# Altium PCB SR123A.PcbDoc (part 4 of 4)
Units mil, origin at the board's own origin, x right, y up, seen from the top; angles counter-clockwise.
Board outline 5500 x 3200 mil, 4 copper layers (Top Layer, Signal Layer 1, Signal Layer 2, Bottom Layer), stack 64.312 mil thick; 295 components, 105 nets, 659 pads, 1365 vias.
Unrouted connection lines stored in the file: 735.
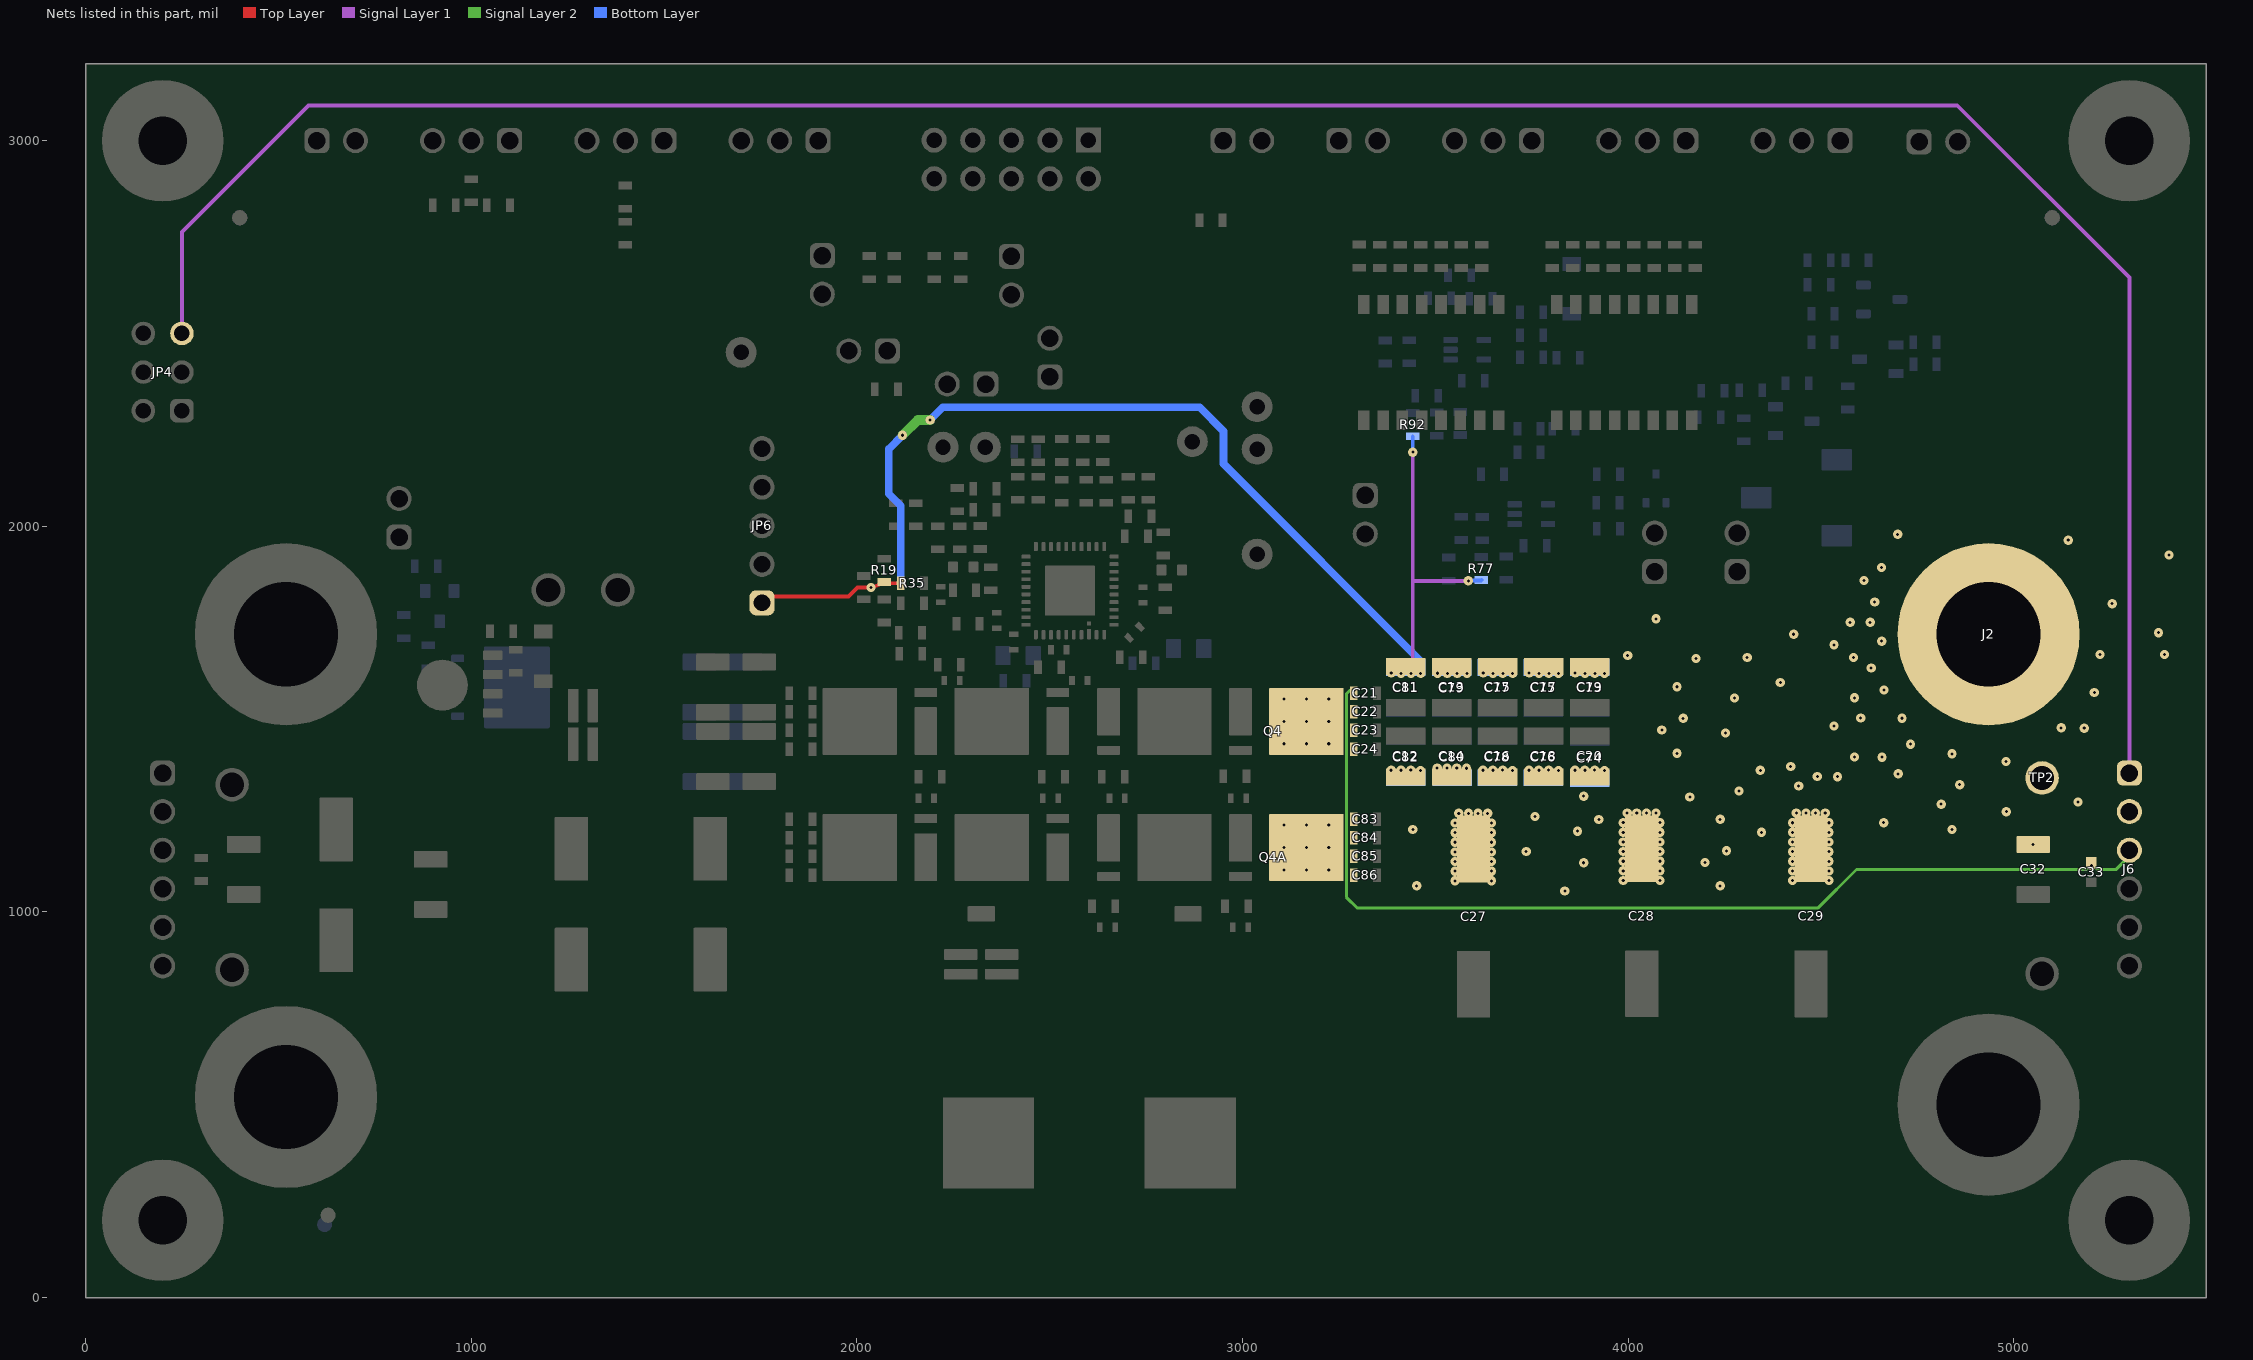
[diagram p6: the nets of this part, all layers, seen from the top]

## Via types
v1: diameter 24, hole 7.87, Top Layer to Bottom Layer, tented both sides, 520 vias
v2: diameter 16, hole 8, Top Layer to Bottom Layer, tented both sides, 418 vias
v3: diameter 24, hole 8, Top Layer to Bottom Layer, tented both sides, 412 vias
v4: diameter 19.68, hole 7.87, Top Layer to Bottom Layer, tented both sides, 12 vias
v5: diameter 16, hole 7.87, Top Layer to Bottom Layer, tented both sides, 2 vias
v6: diameter 34, hole 16, Top Layer to Bottom Layer, tented both sides, 1 vias

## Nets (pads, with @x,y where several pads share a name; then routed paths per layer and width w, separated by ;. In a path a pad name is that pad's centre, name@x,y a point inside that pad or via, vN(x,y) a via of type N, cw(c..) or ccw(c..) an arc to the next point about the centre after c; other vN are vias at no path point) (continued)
VOUT: C11.2 C12.2 C13.2 C14.2 C15.1 C16.1 C17.1 C18.1 C19.1 C20.1 C21.1 C22.1 C23.1 C24.1 C27.2 C28.2 C29.2 C32.2 C33.1 C73.2 C74.2 C75.2 C76.2 C77.1 C78.2 C79.1 C80.1 C81.2 C82.1 C83.2 C84.2 C85.2 C86.2 J2.1 J6.1 J6.2 J6.3 JP4.5 JP6.1 Q4.5-6-7-8 Q4A.5-6-7-8 R19.2 R35.2 R77.2 R92.2 TP2.1 | length 12852.1
  Top Layer w10: JP6.1@1754.31,1801.32 1770.55,1817.56 1978.28,1817.56 2001.74,1841.01 v1(2037.13,1841.01) 2057.47,1848.65 R19.2@2058.29,1848.65 ; R19.2@2081.16,1852.1 2083.29,1852.13 2109.38,1852.6 v3(2114.38,1852.68)
  Signal Layer 1 w10: JP4.5@250,2500 250,2763 578.29,3091.29 4853.71,3091.29 5300,2645 J6.1@5300,1380 ; v1(3441.84,2192.2) 3441.84,1858.5 ; v3(3462.26,1618.71) 3441.84,1618.71 3439.64,1620.91 3439.64,1629.37 3441.84,1631.57 3441.84,1858.5 ; v1(3585.87,1858.5) 3441.84,1858.5
  Signal Layer 2 w8: v2(3289.18,1576.12) 3287.64,1574.59 3279.03,1574.59 3269.67,1565.23 3269.67,1038.33 3298.4,1009.6 4491.84,1009.61 4592.25,1110.01 5189.1,1110.02 5199.4,1120.32 5206.12,1120.32 5215.99,1110.45 5266.2,1110.45 5284.42,1128.67 5284.42,1129.01 5300,1144.59 J6.3@5300,1160
  Signal Layer 2 w25: v3(2118.65,2236.09) 2158.3,2275.74 v3(2190.2,2275.74)
  Bottom Layer w10: v1(3441.84,2192.2) R92.2@3441.84,2233.59 ; v1(3585.87,1858.5) 3586.87,1859.5 3618.66,1859.5 R77.2@3619.66,1860.5
  Bottom Layer w20: v3(2114.38,1852.68) 2114.38,2053.1 2082.75,2084.73 2082.75,2200.19 v3(2118.65,2236.09) ; v3(2190.2,2275.74) 2222.98,2308.53 2889.24,2308.53 2950.99,2246.78 2950.99,2161.99 C81.2@3464.01,1648.97
  other v1: 3836.1,1054.09 3451.98,1067.59 4239.07,1067.59 3884.96,1127.45 4199.7,1128.11 3735.86,1156.51 4255.04,1158.26 5050.72,1174.96 4346.34,1206.44 3868.99,1209.35 3441.84,1214 4662.95,1231.44 3924.34,1239.5 4239.07,1240.16 3759.03,1247.29 4812.13,1279.43 4160.19,1297.69 3884.96,1300.02 4287.93,1313.52 4442.47,1326.68 4490.85,1350.87 4543.32,1350.72 4700.46,1358.13 4342.96,1367.21 4421.75,1376.95 4658.86,1401.13 4587.27,1402 4840,1410 4127.07,1411.35 4732.19,1435 4253,1464.07 4087.7,1471.86 5123.25,1477.4 5183.02,1476.53 4534.39,1481.78 4143.04,1502.01 4710.19,1502.15 4603.21,1502.59 4276.17,1554.85 4587.27,1555.24 5209.27,1568.76 4663.88,1575.64 4127.07,1583.91 4395,1595 4630.38,1632.76 4175.93,1657.27 4308.95,1659.49 4584.92,1659.49 3999.16,1664.74 5223.98,1667.4 5391.07,1667.4 4534.39,1692.61 4657.75,1702.06 4429.66,1720 5375.43,1724.17 4576.2,1750.86 4627.94,1750.86 4072.59,1760 5255.57,1799.17 4639.52,1803.46 4612.04,1859.51 4657,1893 5402.75,1925.61 5141.56,1963.96 4699.22,1979.15
  other v2: 3289.18,1086.12 3289.18,1104.12 3289.18,1135.12 3289.18,1153.12 3289.18,1183.12 3289.18,1201.12 3289.18,1231.12 3289.18,1249.12 3289.18,1413.12 3289.18,1431.12 3289.18,1462.12 3289.18,1480.12 3289.18,1510.12 3289.18,1528.12 3289.18,1558.12
  other v3: 3551.06,1080.56 3646.06,1080.56 3987.7,1081.44 4082.7,1081.44 4426.34,1081.23 4521.34,1081.23 3551.06,1105.56 3646.06,1105.56 3987.7,1106.44 4082.7,1106.44 4426.34,1106.23 4521.34,1106.23 3108.09,1109.13 3165.97,1109.13 3223.84,1109.13 5201.79,1120.32 3551.06,1130.56 3646.06,1130.56 3987.7,1131.44 4082.7,1131.44 4426.34,1131.23 4521.34,1131.23 3551.06,1155.56 3646.06,1155.56 3987.7,1156.44 4082.7,1156.44 4426.34,1156.23 4521.34,1156.23 3108.09,1167 3165.97,1167 3223.84,1167 3551.06,1180.56 3646.06,1180.56 3987.7,1181.44 4082.7,1181.44 4426.34,1181.23 4521.34,1181.23 3551.06,1205.56 3646.06,1205.56 3987.7,1206.44 4082.7,1206.44 4426.34,1206.23 4521.34,1206.23 4840,1213.7 3108.09,1224.87 3165.97,1224.87 3223.84,1224.87 3551.06,1230.56 3646.06,1230.56 3987.7,1231.44 4082.7,1231.44 4426.34,1231.23 4521.34,1231.23 3561.06,1255.56 3586.06,1255.56 3611.06,1255.56 3636.06,1255.56 3997.7,1256.44 4022.7,1256.44 4047.7,1256.44 4072.7,1256.44 4436.34,1256.23 4461.34,1256.23 4486.34,1256.23 4511.34,1256.23 4981,1260 5166.84,1285 4860,1330 3385.74,1367.29 3411.03,1367.29 3436.52,1367.47 3462.01,1366.54 3624.2,1367.29 3649.49,1367.29 3674.98,1367.47 3700.47,1366.54 3743.43,1367.29 3768.72,1367.29 3794.21,1367.47 3819.69,1366.54 3862.66,1367.29 3887.95,1367.29 3913.44,1367.47 3938.92,1366.54 3581.24,1372.45 3504.97,1373.19 3530.26,1373.19 3555.75,1373.38 4980,1390 3108.09,1436.13 3165.97,1436.13 3223.84,1436.13 3108.09,1494 3165.97,1494 3223.84,1494 3108.09,1551.87 3165.97,1551.87 3223.84,1551.87 3531.32,1618.03 3556.81,1618.22 3582.11,1618.22 3385.99,1619.46 3411.48,1618.53 3436.97,1618.71 3505.84,1618.96 3624.45,1619.46 3649.94,1618.53 3675.42,1618.71 3700.72,1618.71 3743.68,1619.46 3769.17,1618.53 3794.65,1618.71 3819.95,1618.71 3862.91,1619.46 3888.4,1618.53 3913.88,1618.71 3939.18,1618.71
pads on no net: FID1.1 FID2.1 FID3.1 FID4.1 FID5.1 FID6.1 H1.1 H2.1 H3.1 H4.1 H5.0 H6.0 H7.0 H8.0 J12.1 J12.2 J12.3 J12.4 J12.7 J12.8 Q6.9@1043.39,1489.09 Q6.9@1043.39,1675.91 Q6.9@1055,1530.14 Q6.9@1055,1582.5 Q6.9@1055,1634.86 Q6.9@1100.28,1530.14 Q6.9@1100.28,1582.5 Q6.9@1100.28,1634.86 Q6.9@1105.59,1582.5 Q6.9@1145.55,1530.14 Q6.9@1145.55,1582.5 Q6.9@1145.55,1634.86 U1.26 U1.34 U1.39

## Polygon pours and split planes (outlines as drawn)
GND on Top Layer "Top Layer-GND 1" (solid, remove dead copper, pour order 116): 3403.64,1434.21 3960.48,1434.22 3967.69,1441.43 3967.69,1543.74 3959.95,1551.48 3403.51,1551.48 3364.99,1590 3334,1590 3325.89,1581.89 3325.89,1408.11 3334,1400 3369.42,1400
NetD1_2 on Top Layer "TOP_LAYER_NETD1_2_P142" (solid, remove dead copper, pour order 142): 1196.24,1745.37 1093.68,1745.37 1082.86,1734.55 1082.86,1710.54 1069.79,1697.47 1052.27,1697.47 1031.95,1677.15 1031.95,1653.75 1079.87,1653.75 1093.58,1667.45 1137.65,1667.45 1179.47,1709.27 1196.24,1709.27
VIN on Top Layer "TOP_LAYER_VIN_P226" (solid, remove dead copper, pour order 226): 1030,2025 1030,1110 1239.04,1110 1285.01,1155.97 1285.01,2025
NetC3_1 on Top Layer "TOP_LAYER_NETC3_1_P148" (solid, remove dead copper, pour order 148): 1187.91,1050.27 1187.92,1260.38 1290,1362.46 1290,2025 1365,2025 1630,1760 2120,1760 2130,1750 2130,1000 2122.34,992.34 1245.84,992.34
SW2 on Top Layer "TOP_LAYER_SW2_P210" (solid, remove dead copper, pour order 210): 2725,875 2593.56,743.56 2593.56,371.34 2593.56,320.78 2664.35,250 3004.91,250 3055,300.09 3055,995 3055,1666.09 2760.79,1666.09 2725,1630.29
GND on Top Layer "Top Layer-GND" (solid, remove dead copper, pour order 219): 2721.55,1676.75 2711.08,1680.1 cw(c2731.21,1688.45) 2711.08,1696.79 2690.03,1718.83 2473.77,1718.83 2465.02,1710.08 2464.98,861.43 2500,826.41 2500,270 2480,250 2230,250 2140.2,339.8 2140.2,1059.8 2099.04,1100.96 1190.19,1100.96 25,1100.96 25,20 5465,20 5474.51,29.51 5474.51,105.49 5474.51,1100.96 3070.53,1100.96 3060,1090.43 3060,296.72 3013.28,250 2750,250 2700.03,299.97 2700.03,864.55 2718.37,882.89
SW1 on Top Layer "TOP_LAYER_SW1_P149" (solid, remove dead copper, pour order 149): 2134.99,1560 2130,1555.01 2130,1375 2135,1370 2214.88,1370 2220,1365 2220,1335 2215,1330 2135.04,1330 2130,1324.96 2130,1090 2140.2,1079.8 2140.2,869.8 2145,865 2440,865 2455,880 2455,1635 2435,1655 2215.09,1655 2205,1644.91 2205,1575 2190,1560
AGND on Top Layer "TOP_LAYER_AGND_P220" (solid, pour order 220): -12.05,2035 1359.21,2035 1624.2,1770 2124.94,1770 2135,1759.94 2135,1682.73 3093.26,1682.73 3110.53,1700 4339.98,1700 4659.42,2019.44 5487.95,2019.44 5487.95,3200.48 -12.05,3200.48
NetL1_1 on Top Layer "TOP_LAYER_NETL1_1_P211" (solid, remove dead copper, pour order 211): 2582.79,745.36 2468.15,860 2150,860 2146.58,856.58 2146.58,328.42 2225,250 2513.14,250 2582.79,319.66
VOUT on Top Layer "TOP_LAYER_VOUT_P198" (solid, pour order 198): 4451.92,1801.92 3191.92,1801.92 3065,1675 3065,1015 3076.9,1003.1 4463.1,1003.1 4565,1105 5500,1105 5500,2010 4660,2010
GND on Top Layer "TOP_LAYER_GND_P067" (solid, remove dead copper, pour order 67): 1630.78,1590 1547,1506.22 1547,1479.78 1626.78,1400 1840,1400 1845.11,1405.11 1845.11,1584.89 1840,1590
VIN on Top Layer "TOP_LAYER_VIN_P221" (solid, remove dead copper, pour order 221): 20,2030 1020,2030 1019.97,1400 1040.1,1400 1040.1,1199.77 1020,1199.77 1020,1110 20,1110
GND on Signal Layer 1 "SIGNAL_LAYER_1_GND_P181" (solid, remove dead copper, pour order 181): 35,2025 20,2010 20,55 50,25 5442.5,25 5487.95,70.45 5487.95,1976.67 5454.61,2010 4670,2010 4356.91,1696.91 1698.09,1696.91 1370,2025
AGND on Signal Layer 1 "SIGNAL_LAYER_1_AGND_P182" (solid, remove dead copper, pour order 182): -3.94,2030.48 1379.02,2030.48 1707.51,1701.99 4346.34,1701.99 4662.95,2018.63 5496.06,2018.63 5496.06,3199.67 -3.94,3199.67
GND on Bottom Layer "Bottom Layer-GND 1" (solid, remove dead copper, pour order 189): 3399.93,1422.05 3948.32,1422.05 3967.69,1441.43 3967.69,1545 3953.39,1559.29 3407.25,1559.29 3376.54,1590 3335,1590 3325,1580 3325,1405 3332,1398 3375.89,1398
VIN on Bottom Layer "BOTTOM_LAYER_VIN_P227" (solid, remove dead copper, pour order 227): 1030,2025 1030,1125 1055,1100 1205,1100 1205,1260 1285.01,1340.01 1285.01,2025
VOUT on Bottom Layer "BOTTOM_LAYER_VOUT_P203" (solid, pour order 203): 4429.66,1779.66 3184.66,1779.66 3065,1660 3065,1039.07 3096.44,1007.63 4481.6,1007.64 4588.96,1115 5500,1115 5500,2010 4660,2010
AGND on Bottom Layer "BOTTOM_LAYER_AGND_P222" (solid, pour order 222): -12.05,2030.48 1363.72,2030.48 1624.2,1770 2124.94,1770 2135,1759.94 2135,1637.43 3113.49,1637.43 3120,1643.94 3120,1690 3130,1700 4339.98,1700 4659.42,2019.44 5487.95,2019.44 5487.95,3200.48 -12.05,3200.48
GND on Bottom Layer "Top Layer-GND" (solid, remove dead copper, pour order 209): 35,20 5475,20 5484.51,29.51 5484.51,105.49 5484.51,1105 3112.56,1105 3066.38,1142.66 3066.38,1684.48 3032.03,1718.83 2168.71,1718.83 2140,1690.12 2140,1129.99 2120,1110 35,1110
NetC3_1 on Bottom Layer "BOTTOM_LAYER_NETC3_1_P208" (solid, remove dead copper, pour order 208): 1183,1056.2 1183,1245.46 1290,1352.46 1290,2025 1365,2025 1630,1760 2120,1760 2130,1750 2130,1100 2039.6,1009.6 1229.6,1009.61
VIN on Bottom Layer "BOTTOM_LAYER_VIN_P216" (solid, remove dead copper, pour order 216): 20,2020 1000,2020 1020,2000 1020,1115 1015,1110 20,1110
GND on Bottom Layer "Bottom Layer-GND" (solid, remove dead copper, pour order 193): 1840,1400 1850,1410 1850,1575 1840,1585 1590.59,1585 1542,1536.41 1542,1506.22 1542,1479.78 1542,1450.47 1592.47,1400
GND on Signal Layer 2 "Signal Layer 2-GND" (solid, remove dead copper, pour order 206): 3326.01,1406 3331.01,1401 3356,1401 3361,1406 3361,1466 3365.97,1470.97 3619.65,1471.04 3619.65,1471.01 3659.62,1471.01 3716.21,1471.02 3756.18,1471.02 3941.46,1471.07 3950.34,1479.95 3950.34,1505.57 3939.89,1516.03 3716.21,1516.03 3716.21,1516.01 3619.65,1516.01 3619.65,1515.98 3366.02,1515.98 3361,1521 3361,1581 3356,1586 3331,1586 3326.01,1581.01
VIN on Signal Layer 2 "SIGNAL_LAYER_2_VIN_P225" (solid, remove dead copper, pour order 225): 1030,2025 1030,1125 1055,1100 1205,1100 1205,1260 1285.01,1340.01 1285.01,2025
GND on Signal Layer 2 "SIGNAL_LAYER_2_GND_P213" (solid, remove dead copper, pour order 213): 1540.02,1509.98 1545,1514.96 1805.03,1515.03 1810,1520 1810,1580 1815,1585 1839.99,1585 1844.99,1580 1844.99,1404.99 1840,1400 1815,1400 1810,1405 1810,1465 1804.98,1470.02 1545,1470.02 1540.02,1475
NetC3_1 on Signal Layer 2 "SIGNAL_LAYER_2_NETC3_1_P215" (solid, remove dead copper, pour order 215): 1183,1061.34 1183,1250.21 1290,1357.21 1290,2025 1365,2025 1630,1760 2120,1760 2130,1750 2130,1062.37 2072.63,1005 1239.34,1005
VOUT on Signal Layer 2 "SIGNAL_LAYER_2_VOUT_P212" (solid, pour order 212): 4440,1790 3195,1790 3065,1660 3065,1051.62 3108.99,1007.63 4474.96,1007.64 4572.32,1105 5500,1105 5500,2010 4660,2010
GND on Signal Layer 2 "Top Layer-GND" (solid, remove dead copper, pour order 217): 35,20 5475,20 5484.51,29.51 5484.51,105.49 5484.51,1105 3112.56,1105 3066.38,1142.66 3066.38,1684.48 3032.03,1718.83 2168.71,1718.83 2120,1670.12 2120,1110 35,1110
AGND on Signal Layer 2 "SIGNAL_LAYER_2_AGND_P223" (solid, pour order 223): -12.05,2030.48 1363.72,2030.48 1624.2,1770 2124.94,1770 2135,1759.94 2135,1620.96 3110.9,1620.96 3120,1630.07 3120,1690 3130,1700 4339.98,1700 4659.42,2019.44 5487.95,2019.44 5487.95,3200.48 -12.05,3200.48
VIN on Signal Layer 2 "SIGNAL_LAYER_2_VIN_P218" (solid, remove dead copper, pour order 218): 20,1990 50,2020 1000,2020 1020,2000 1020,1135 995,1110 50,1110 20,1140

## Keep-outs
Keep-Out Layer:
  text ".Layer_Name" at 577,-858.49 h60

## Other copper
Top Layer:
  pour cut-out: 5258.88,1060.24 cw(c5300.24,1060.24) 5300.24,1101.59 cw(c5300.24,1060.24) 5341.59,1060.24 cw(c5300.24,1060.24) 5300.24,1018.89 cw(c5300.24,1060.24)
  pour cut-out: 5258.88,1160.24 cw(c5300.24,1160.24) 5300.24,1201.59 cw(c5300.24,1160.24) 5341.59,1160.24 cw(c5300.24,1160.24) 5300.24,1118.89 cw(c5300.24,1160.24)
  pour cut-out: 5223.45,1120.32 cw(c5201.94,1120.32) 5201.94,1098.81 cw(c5201.94,1120.32) 5180.43,1120.32 cw(c5201.94,1120.32) 5201.94,1141.82 cw(c5201.94,1120.32)
  pour cut-out: 5179.77,1084.31 cw(c5201.28,1084.31) 5201.28,1105.81 cw(c5201.28,1084.31) 5222.79,1084.31 cw(c5201.28,1084.31) 5201.28,1062.8 cw(c5201.28,1084.31)
  pour cut-out: 158.75,1060.28 cw(c200.1,1060.28) 200.1,1101.63 cw(c200.1,1060.28) 241.46,1060.28 cw(c200.1,1060.28) 200.1,1018.93 cw(c200.1,1060.28)
  pour cut-out: 278.75,1085.03 cw(c300.26,1085.03) 300.26,1106.54 cw(c300.26,1085.03) 321.77,1085.03 cw(c300.26,1085.03) 300.26,1063.52 cw(c300.26,1085.03)
  pour cut-out: 5223.45,1120.32 5223.45,1148.95 5180.14,1148.95 5180.14,1120.32
  pour cut-out: 5179.77,1084.31 5179.77,1084.3 5179.77,1057.18 5223.08,1057.18 5223.08,1084.31
  pour cut-out: 278.75,1085.03 278.75,1085.02 278.75,1063.51 322.06,1063.51 322.06,1085.03
  pour cut-out: 1009.97,1199.77 1009.97,1111.27 1040.06,1111.27 1040.06,1199.77
  pour cut-out: 1010.2,1492.25 1010.2,1400 1040.29,1400 1040.29,1492.25
  text ".Layer_Name" at 577,-858.49 h60
Signal Layer 1:
  pour cut-out: 5258.88,1060.24 cw(c5300.24,1060.24) 5300.24,1101.59 cw(c5300.24,1060.24) 5341.59,1060.24 cw(c5300.24,1060.24) 5300.24,1018.89 cw(c5300.24,1060.24)
  pour cut-out: 278.75,1085.03 cw(c300.26,1085.03) 300.26,1106.54 cw(c300.26,1085.03) 321.77,1085.03 cw(c300.26,1085.03) 300.26,1063.52 cw(c300.26,1085.03)
  pour cut-out: 5179.56,1084.96 cw(c5201.06,1084.96) 5201.06,1106.47 cw(c5201.06,1084.96) 5222.57,1084.96 cw(c5201.06,1084.96) 5201.06,1063.46 cw(c5201.06,1084.96)
  pour cut-out: 158.17,1159.67 cw(c199.52,1159.67) 199.52,1201.03 cw(c199.52,1159.67) 240.87,1159.67 cw(c199.52,1159.67) 199.52,1118.32 cw(c199.52,1159.67)
  pour cut-out: 158.75,1060.28 cw(c200.1,1060.28) 200.1,1101.63 cw(c200.1,1060.28) 241.46,1060.28 cw(c200.1,1060.28) 200.1,1018.93 cw(c200.1,1060.28)
  pour cut-out: 965.23,1498.34 965.23,1100 1089.11,1100 1089.11,1498.34
  text ".Layer_Name" at 577.07,-859.59 h60
Signal Layer 2:
  pour cut-out: 1293.44,1545.08 cw(c1314.95,1545.08) 1314.95,1566.59 cw(c1314.95,1545.08) 1336.46,1545.08 cw(c1314.95,1545.08) 1314.95,1523.58 cw(c1314.95,1545.08)
  pour cut-out: 1243.46,1545 cw(c1264.97,1545) 1264.97,1566.51 cw(c1264.97,1545) 1286.47,1545 cw(c1264.97,1545) 1264.97,1523.5 cw(c1264.97,1545)
  pour cut-out: 5179.43,1118.86 cw(c5200.94,1118.86) 5200.94,1140.37 cw(c5200.94,1118.86) 5222.45,1118.86 cw(c5200.94,1118.86) 5200.94,1097.36 cw(c5200.94,1118.86)
  pour cut-out: 5179.97,1085.27 cw(c5201.47,1085.27) 5201.47,1106.77 cw(c5201.47,1085.27) 5222.98,1085.27 cw(c5201.47,1085.27) 5201.47,1063.76 cw(c5201.47,1085.27)
  pour cut-out: 5258.4,1059.72 cw(c5299.75,1059.72) 5299.75,1101.07 cw(c5299.75,1059.72) 5341.11,1059.72 cw(c5299.75,1059.72) 5299.75,1018.37 cw(c5299.75,1059.72)
  pour cut-out: 5258.88,1160.24 cw(c5300.24,1160.24) 5300.24,1201.59 cw(c5300.24,1160.24) 5341.59,1160.24 cw(c5300.24,1160.24) 5300.24,1118.89 cw(c5300.24,1160.24)
  pour cut-out: 5258.4,1059.72 cw(c5299.75,1059.72) 5299.75,1101.07 cw(c5299.75,1059.72) 5341.11,1059.72 cw(c5299.75,1059.72) 5299.75,1018.37 cw(c5299.75,1059.72)
  pour cut-out: 5258.88,1160.24 cw(c5300.24,1160.24) 5300.24,1201.59 cw(c5300.24,1160.24) 5341.59,1160.24 cw(c5300.24,1160.24) 5300.24,1118.89 cw(c5300.24,1160.24)
  pour cut-out: 278.84,1086.15 cw(c300.34,1086.15) 300.34,1107.66 cw(c300.34,1086.15) 321.85,1086.15 cw(c300.34,1086.15) 300.34,1064.65 cw(c300.34,1086.15)
  pour cut-out: 279.08,1133.56 cw(c300.59,1133.56) 300.59,1155.06 cw(c300.59,1133.56) 322.09,1133.56 cw(c300.59,1133.56) 300.59,1112.05 cw(c300.59,1133.56)
  pour cut-out: 158.17,1159.67 cw(c199.52,1159.67) 199.52,1201.03 cw(c199.52,1159.67) 240.87,1159.67 cw(c199.52,1159.67) 199.52,1118.32 cw(c199.52,1159.67)
  pour cut-out: 158.75,1060.28 cw(c200.1,1060.28) 200.1,1101.63 cw(c200.1,1060.28) 241.46,1060.28 cw(c200.1,1060.28) 200.1,1018.93 cw(c200.1,1060.28)
  pour cut-out: 5185.51,1128.57 4586.56,1128.57 4479.94,1021.95 3305.56,1021.95 3281.4,1046.11 3281.4,1549.27 3289.18,1557.05 3289.18,1558.12 3289.18,1576.12 3281.4,1583.9 3265.89,1583.9 3253.8,1571.8 3253.8,1047.82 3239.47,1033.49 3239.47,1026.25 3285.3,980.42 4509.63,980.42 4602.3,1073.08 4603.21,1073.08 5183.24,1073.08
  pour cut-out: 1172.8,1111 223.08,1111 223.08,1068.2 1172.8,1068.2
  pour cut-out: 5184.55,1124.38 5257.61,1124.38 5281.81,1148.59 5300.71,1129.69 5302.75,1129.69 5302.75,1128.81 5275.53,1101.59 5184.55,1102.62
  pour cut-out: 1250.1,1529.87 1272.85,1552.62 1327.06,1552.62 1327.06,1500.04 1279.93,1500.04
  pour cut-out: 5206.98,1056.72 5235.24,1084.98 5256.08,1084.98 5277.26,1063.79 5296.16,1082.7 5298.2,1082.7 5298.2,1083.58 5270.98,1110.8 5210.11,1110.11 5173.14,1073.14
  text ".Layer_Name" at 575.75,-859.59 h60
Bottom Layer:
  pour cut-out: 278.75,1085.03 cw(c300.26,1085.03) 300.26,1106.54 cw(c300.26,1085.03) 321.77,1085.03 cw(c300.26,1085.03) 300.26,1063.52 cw(c300.26,1085.03)
  pour cut-out: 5180.58,1084.55 cw(c5202.08,1084.55) 5202.08,1106.06 cw(c5202.08,1084.55) 5223.59,1084.55 cw(c5202.08,1084.55) 5202.08,1063.05 cw(c5202.08,1084.55)
  pour cut-out: 5258.4,1059.72 cw(c5299.75,1059.72) 5299.75,1101.07 cw(c5299.75,1059.72) 5341.11,1059.72 cw(c5299.75,1059.72) 5299.75,1018.37 cw(c5299.75,1059.72)
  pour cut-out: 5180.63,1120.65 cw(c5202.14,1120.65) 5202.14,1142.15 cw(c5202.14,1120.65) 5223.64,1120.65 cw(c5202.14,1120.65) 5202.14,1099.14 cw(c5202.14,1120.65)
  pour cut-out: 5258.88,1160.24 cw(c5300.24,1160.24) 5300.24,1201.59 cw(c5300.24,1160.24) 5341.59,1160.24 cw(c5300.24,1160.24) 5300.24,1118.89 cw(c5300.24,1160.24)
  pour cut-out: 1293.05,1544.88 cw(c1314.56,1544.88) 1314.56,1566.38 cw(c1314.56,1544.88) 1336.06,1544.88 cw(c1314.56,1544.88) 1314.56,1523.37 cw(c1314.56,1544.88)
  pour cut-out: 1243.37,1544.97 cw(c1264.88,1544.97) 1264.88,1566.48 cw(c1264.88,1544.97) 1286.39,1544.97 cw(c1264.88,1544.97) 1264.88,1523.46 cw(c1264.88,1544.97)
  pour cut-out: 158.17,1159.67 cw(c199.52,1159.67) 199.52,1201.03 cw(c199.52,1159.67) 240.87,1159.67 cw(c199.52,1159.67) 199.52,1118.32 cw(c199.52,1159.67)
  pour cut-out: 158.75,1060.28 cw(c200.1,1060.28) 200.1,1101.63 cw(c200.1,1060.28) 241.46,1060.28 cw(c200.1,1060.28) 200.1,1018.93 cw(c200.1,1060.28)
  text ".Layer_Name" at 577,-858.49 h60

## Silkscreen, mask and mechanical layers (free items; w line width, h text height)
Top Overlay:
  lines w6: 1991.97,2190.64 2143.27,2190.64 2205.19,2128.72 2272.36,2128.72 2280,2121.08 ; 2150.93,1622.5 2156.37,1617.07 ; 2156.37,1616.81 2186.72,1616.81 ; 2182.41,1925.12 2187.12,1920.42 2262.16,1920.42 2268.78,1913.8 ; 2187.18,1616.53 2200.52,1603.2 ; 2228.42,1876.39 2233.85,1870.96 2233.85,1870.7 2264.21,1870.7 2264.3,1870.42 2264.67,1870.42 2278,1857.08 ; 2626,1605.81 2630.7,1610.52 2740.37,1610.52 2748.56,1618.71 ; 2816,1870.42 2840.17,1846.24 2863.33,1846.24 2938.38,1846.24 2952.97,1831.65 2971.85,1831.65
  lines w10: 995.21,1151.84 995.21,1448.35 ; 1056.06,1150.99 1056.06,1449.8
  text "FLT" at 2962.38,2843.67 h35 r90
  text "VIN" at 1316.8,2821.21 h35 r90
  text "AGND" at 713,2818.85 h35 r90
  text "VEXT" at 617.09,2818 h35 r90
  text "CDC" at 3259.94,2818.33 h35 r90
  text "AGND" at 3367.13,2818.33 h35 r90
  text "VCC2" at 1716.8,2815.55 h35 r90
  text "ILIM" at 1788.41,2815.55 h35 r90
  text "VCC2" at 4370.08,2816.35 h35 r90
  text "SYNC" at 4472.01,2816.35 h35 r90
  text "AGND" at 4577.05,2816.35 h35 r90
  text "VCC1" at 4776.03,2815.42 h35 r90
  text "GND" at 4875.08,2814.32 h35 r90
  text "AGND" at 3068.23,2812.16 h35 r90
  text "VCC2" at 3574.61,2811.67 h35 r90
  text "MODE" at 3669,2811.67 h35 r90
  text "AGND" at 3769.61,2811.67 h35 r90
  text "VCC2" at 3970.08,2811.67 h35 r90
  text "DTRK" at 4069,2811.67 h35 r90
  text "AGND" at 4169,2811.67 h35 r90
  text "AGND" at 1549,2811 h35 r90
  text "AGND" at 1916.34,2809.55 h35 r90
  text "COMP" at 1837.29,2807.64 h35 r90
  text "VIN" at 918.7,2691.76 h35 r90
  text "CFG3" at 2475.92,2684.91 h35
  text "CFG4" at 1727.16,2681.85 h35
  text "AGND" at 1116.61,2664.14 h35 r90
  text "AGND" at 2468.16,2589.99 h35
  text "AGND" at 1728.81,2585.15 h35
  text "NRST" at 1416,2576 h35 r90
  text "EN/UVLO" at 1016,2559.94 h35 r90
  text "VOUT" at 332.19,2487.32 h35
  text "AGND" at 2561.16,2469.78 h35
  text "AGND" at 2177.08,2427.66 h30
  text "RT" at 2322.11,2427.45 h30
  text "VIN" at 332.19,2385.55 h35
  text "SLOPE" at 2560.06,2376.48 h35
  text "VCC2" at 1629.17,2343.2 h35
  text "AGND" at 3111.3,2286.86 h35
  text "SYNC" at 2808.26,2285.38 h35
  text "VEXT" at 335.47,2280.89 h35
  text "AGND" at 2143.27,2275.44 h30
  text "COMP" at 2272.29,2275.44 h30
  text "VCC2" at 1555.53,2190.13 h35
  text "SS/ATRK" at 3113.89,2184.75 h35
  text "R_FB" at 1555.53,2081 h35
  text "CFG2" at 3380.61,2061.87 h35
  text "AGND" at 877.59,2058.87 h35
  text "BIAS" at 2986,2011 h35
  text "AGND" at 1555.53,1983.61 h35
  text "AGND" at 3380.61,1969.32 h35
  text "DRV1" at 877.59,1962.71 h35
  text "ISNSP" at 1106.61,1936.17 h35
  text "ISNSN" at 1310.53,1933.4 h35
  text "AC_B" at 1555.53,1883.03 h35
  text "AC_A" at 1555.53,1783.36 h35
  text "VOUT" at 5222.99,1707.99 h50
  text "VIN" at 104.46,1691.35 h50
  text "Max.17A" at 5193.27,1579.13 h35
  text "Max.26A" at 61,1570 h35
  text "VOUT" at 4470.99,1523.64 h35
  text "12V" at 5259.06,1521.06 h35
  text "9-30V" at 61,1511 h35
  text "CUT HERE" at 1043.35,1165.87 h35 r90
  text "S+" at 5375.23,1142.57 h35
  text "S+" at 83.32,1128.81 h35
  text "S-" at 5376,1046 h35
  text "S-" at 83.32,1041.04 h35
  text "SW1" at 2371.83,1003.29 h35
  text "CSA" at 2098.48,911.03 h35
  text "SW2" at 2746.88,897.31 h35
  text "CSB" at 2098.48,853.78 h35
  text "GND" at 1844.56,687.28 h35
  text "GND" at 4481.62,609.23 h35
  text "GND" at 89.32,481 h50
  text "GND" at 5231.77,476 h50
  text ".PRJ_title" at 1123.85,376 h60
  text "'.PRJ_Number'" at 1123.85,292.23 h40
  text "REV..PCB_Rev" at 1365.78,292.45 h40
  text ".Layer_Name" at 577,-858.49 h60
Bottom Overlay:
  text "Optional external components / Beard board area" at 4230.18,2753.8 h35
  text ".Layer_Name" at 577,-858.49 h60
Top Paste:
  text ".Layer_Name" at 577,-858.49 h60
Bottom Paste:
  text ".Layer_Name" at 577,-858.49 h60
Top Solder:
  text ".Layer_Name" at 577,-858.49 h60
  text ".Layer_Name" at 577,-858.49 h60
Bottom Solder:
  text ".Layer_Name" at 577,-858.49 h60
Drill Guide:
  text ".Layer_Name" at 577,-858.49 h60
M1 Board Outline:
  the board outline again, w10
  text ".Layer_Name" at 577,-858.49 h60
M2 Board Dimensions:
  rectangle: 0,-275 125,-150
  rectangle: 125,-400 500,-275
  lines w7: 0,-275 1000,-275 ; 125,-400 125,-150 ; 250,-400 250,-150 ; 500,-400 500,-150 ; 750,-400 750,-150 ; 0,-400 1000,-400 1000,-150 0,-150 0,-400
  text ".Layer_Name" at 577,-858.49 h60
M3 3D STEP Top:
  text ".Layer_Name" at 577,-858.49 h60
M4 3D STEP Bottom:
  text ".Layer_Name" at 577,-858.49 h60
Top M5 Assembly Top/M6 Assembly Bottom:
  lines w10: -292,-930.17 6308,-930.17 ; -292,-726.83 6310,-726.83 ; -292,-523.5 -292,-1133.5 3713,-1133.5 6310,-1133.5 6310,-523.5 -291.5,-523.5 -291.5,-1133.5 1284,-1133.5 ; 2173,-1133.5 2173,-523.5 ; 3440,-726.83 3440,-523.5 ; 4280,-726.83 4280,-523.5 ; 4902,-1140 4902,-937.17
  text "COMPONENTS MARKED 'DNP' SHOULD NOT BE POPULATED." at 1153.5,-318.5 h60
  text "ASSEMBLY VARIANT:" at 1153,-434 h60
  text ".VariantName" at 2189,-434 h60
  text "PCB VIEWED FROM TOP SIDE" at -228.5,-655.67 h60
  text "BOARD #:" at 2248,-655.67 h60
  text ".PRJ_Number" at 2793.5,-655.67 h60
  text "REV:" at 3638,-655.67 h60
  text ".PCB_Rev" at 3929.5,-655.67 h60
  text "SVN REV:" at 4476,-655.67 h60
  text ".VersionControl_RevNumber" at 4982,-655.67 h60
  text "TID #:" at 2248,-859 h60
  text ".TID" at 2793.5,-859 h60
  text "PLOT NAME =" at -228.5,-1064.34 h60
  text ".plot_File_Name" at 577,-1064.34 h60
  text "GENERATED    :" at 2250,-1064.34 h60
  text ".Print_Date" at 3119.5,-1064.34 h60
  text ".Print_Time" at 3848.5,-1064.34 h60
  text "TEXAS INSTRUMENTS" at 5113,-1064.34 h60
Bottom M5 Assembly Top/M6 Assembly Bottom:
  lines w10: -292.5,-727.33 6309.5,-727.33 ; -290.5,-930.67 6309.5,-930.67 ; 1115.5,-1140.5 1115.5,-937.67 ; 1737.5,-727.33 1737.5,-524 ; 2577.5,-727.33 2577.5,-524 ; 3844.5,-1134 3844.5,-524 ; 4733.5,-1134 6309,-1134 6309,-524 -292.5,-524 -292.5,-1134 2304.5,-1134 6309.5,-1134 6309.5,-524
  text "COMPONENTS MARKED 'DNP' SHOULD NOT BE POPULATED." at 6102,-318 h60
  text ".VariantName" at 5058,-434 h60
  text "ASSEMBLY VARIANT:" at 6097,-434 h60
  text ".VersionControl_RevNumber" at 1035.5,-656.17 h60
  text "SVN REV:" at 1541.5,-656.17 h60
  text ".PCB_Rev" at 2088,-656.17 h60
  text "REV:" at 2379.5,-656.17 h60
  text ".PRJ_Number" at 3224,-656.17 h60
  text "BOARD #:" at 3769.5,-656.17 h60
  text "PCB VIEWED FROM BOTTOM SIDE" at 6246,-656.17 h60
  text ".TID" at 3224,-859.5 h60
  text "TID #:" at 3769.5,-859.5 h60
  text "TEXAS INSTRUMENTS" at 904.5,-1064.84 h60
  text ".Print_Time" at 2169,-1064.84 h60
  text ".Print_Date" at 2898,-1064.84 h60
  text "GENERATED    :" at 3767.5,-1064.84 h60
  text ".plot_File_Name" at 5440.5,-1064.84 h60
  text "PLOT NAME =" at 6246,-1064.84 h60
M9 Title Sheet:
  drawing of 57 lines, arcs and shapes, not listed
  text "1" at 739.84,8036.5 h70
  text "2" at 3235.5,8036.5 h70
  text "3" at 5724.84,8036.5 h70
  text "4" at 8231.51,8036.5 h70
  text "5" at 10730.5,8036.5 h70
  text "6" at 13235.5,8036.5 h70
  text "A" at -416.5,6893.5 h70
  text "A" at 14383.5,6893.5 h70
  text "B" at -416.5,4513.5 h70
  text "B" at 14383.5,4513.5 h70
  text "C" at -416.5,2138.5 h70
  text "C" at 14383.5,2138.5 h70
  text "PROJECT TITLE:" at 11343.5,277.5 h45
  text ".PRJ_Title" at 11393.5,144.17 h70
  text "DESIGNED FOR:" at 11343.5,-23.5 h45
  text ".PRJ_Customer" at 11393.5,-163.5 h70
  text "D" at -416.5,-231.5 h70
  text "D" at 14383.5,-231.5 h70
  text "FILE NAME:" at 11343.5,-323.5 h45
  text ".PCB_File_Name_No_Path" at 11393.5,-443.5 h70
  text "Texas Instruments (TI) and/or its licensors do not warrant the accuracy or completeness of this specification" at 6374,-605.34 h45
  text "ENGINEER:" at 11343.5,-613.5 h45
  text "LAYOUT BY:" at 12848.5,-613.5 h45
  text "or any information contained therein. TI and/or its licensors do not warrant that this design will meet" at 6329.01,-718 h45
  text ".PRJ_Engineer" at 11393.5,-768.49 h70
  text ".PCB_Layout" at 12899,-768.49 h70
  text "the specifications, will be suitable for your application or fit for any particular purpose, or will operate in" at 6329.01,-830.67 h45
  text ".Layer_Name" at 577,-858.49 h60
  text "ALTIUM DESIGNER VERSION:" at 12848.5,-923.5 h45
  text "an implementation. TI and/or its licensors do not warrant that the design is production worthy. You should" at 6329.01,-943.33 h45
  text "completely validate and test your design implementation to confirm the system functionality for your application." at 6374,-1056 h45
  text ".print_Scale" at 11393.5,-1056.83 h70
  text ".Application_BuildNumber" at 12899,-1056.83 h70
  text "1" at 739.84,-1263.5 h70
  text "2" at 3235.5,-1263.5 h70
  text "3" at 5724.84,-1263.5 h70
  text "4" at 8231.51,-1263.5 h70
  text "5" at 10730.5,-1263.5 h70
  text "6" at 13235.5,-1263.5 h70
M10 Fab Notes:
  drawing of 189 lines, arcs and shapes, not listed
  text "DESIGN INFORMATION" at 12382.02,6356.17 h60
  text "MIN. TRACK WIDTH:" at 11737.46,6224.05 h60
  text "8" at 12833.7,6224.05 h60
  text "MIL" at 12988.46,6224.05 h60
  text "7.874" at 12667.32,6102.36 h60
  text "MIN. CLEARANCE:" at 11737.46,6099.92 h60
  text "MIL" at 12988.46,6099.92 h60
  text "16" at 12628,5977 h60
  text "MIN. VIA PAD SIZE:" at 11737.46,5975.8 h60
  text "MIL" at 12988.46,5975.8 h60
  text "0.05mm (2MIL)" at 12432.46,5845.9 h60
  text "MINIMUM ANNULAR RING" at 11408.23,5837.67 h60
  text "EXTERNAL" at 13140.46,5837.67 h60
  text "PER" at 11608.23,5727.55 h60
  text "IPC-D-275 CLASS 2 LEVEL C" at 11828.23,5727.54 h60
  text "MIL, HOLES" at 13316.46,5627.07 h60
  text "+/-" at 12924,5618.48 h60
  text "+/-" at 13778,5618.48 h60
  text "REGISTRATION TOLERANCES:" at 11408.23,5617.42 h60
  text "METAL" at 12608,5617.42 h60
  text "5" at 13184.2,5617.42 h60
  text "3" at 14017.2,5617.42 h60
  text "MIL" at 14133.46,5617.42 h60
  text "HOLE SIZE TOLERANCE (UNLESS OTHERWISE SPECIFIED):" at 11408.23,5519.1 h60
  text "+/-" at 13778,5516.23 h60
  text "3" at 14017.2,5515.17 h60
  text "MIL" at 14133.46,5515.17 h60
  text "MATERIAL:" at 11333.46,5377.52 h60
  text "FR-4 High Tg" at 12319.9,5249 h60
  text "X" at 12175.46,5241.01 h60
  text "FR-4" at 11754.46,5236.49 h60
  text "OTHER" at 13242.46,5236.49 h60
  text "65 MIL (1.65mm) +/-10%" at 12074.56,5093.46 h60
  text "X" at 11954.46,5091.01 h60
  text "THICKNESS:" at 11408.23,5085.24 h60
  text "OTHER" at 13359.46,5085.24 h60
  text "TOLERANCE:" at 11408.23,4946.92 h60
  text "X" at 12256.46,4946.92 h60
  text "ANSI IPC-6012 TYPE 3 CLASS 2" at 12434.48,4946.92 h60
  text "OTHER +/-" at 12434.46,4802.73 h60
  text "BOW & TWIST:" at 11408.23,4657.54 h60
  text "X" at 12256.46,4657.54 h60
  text "ANSI IPC-6012 TYPE 3 CLASS 2" at 12434.48,4657.54 h60
  text "OTHER +/-" at 12434.46,4510.85 h60
  text "DRILLING:" at 11333.46,4380.23 h60
  text "NC_DRILL FILES" at 13094.46,4275.04 h60
  text "REFERENCE:" at 11408.23,4271.1 h60
  text "X" at 12065.46,4271.01 h60
  text "AS SHOWN" at 12243.46,4271.1 h60
  text "X" at 12966.46,4271.1 h60
  text "OTHER" at 13392.46,4128.85 h60
  text "PTH COPPER THICKNESS:" at 11407.91,4125.32 h60
  text "X" at 12547.14,4125.32 h60
  text "20-30 um" at 12675.14,4125.32 h60
  text "BOARD FINISH:" at 11333.46,3977.73 h60
  text "SILKSCREEN:" at 11488.68,3867.6 h60
  text "X" at 12446.46,3867.6 h60
  text "TOP" at 12563.46,3867.6 h60
  text "X" at 12956.46,3867.6 h60
  text "BOTTOM" at 13074.46,3867.6 h60
  text "SILKSCREEN COLOR:" at 11488.68,3712.41 h60
  text "X" at 12445.46,3712.41 h60
  text "WHITE" at 12563.46,3712.41 h60
  text "OTHER" at 13074.46,3712.41 h60
  text "X" at 12576.46,3568.96 h60
  text "GREEN" at 12694.46,3568.96 h60
  text "OTHER" at 13312.46,3568.96 h60
  text "SOLDER RESIST COLOR:" at 11488.68,3562.1 h60
  text "X" at 12576.46,3414.71 h60
  text "MATTE" at 12694.46,3414.71 h60
  text "SEMI-GLOSS" at 13312,3414.07 h60
  text "IMMERSION GOLD (ENIG)" at 12394.46,3241.94 h60
  text "ENEPIG" at 13732,3234.72 h60
  text "SURFACE FINISH:" at 11333.46,3233.72 h60
  text "X" at 12216.46,3233.72 h60
  text "IMM. TIN/SILVER OR EQUIV" at 11663,3096.4 h60
  text "OTHER" at 13094.46,3092.47 h60
  text "ARRAY/PANEL:" at 11333.46,2937.09 h60
  text "CUT AND TRIM PER M1 BOARD OUTLINE" at 12394.46,2928.87 h60
  text "N.C. ROUTE" at 12394.46,2792.9 h60
  text "X" at 13082.46,2792.9 h60
  text "V. SCORE" at 13260.46,2792.9 h60
  text "CERTIFICATION:" at 11333.46,2663.77 h60
  text "MATERIALS AND WORKMANSHIP FOR ALL PCBS" at 12058.46,2663.77 h60
  text "TO MEET OR EXCEED THE REQUIREMENTS OF:" at 12058.46,2569.71 h60
  text "X" at 11695.97,2441.08 h60
  text "ANSI IPC-A-600F CLASS ->" at 11823.96,2441.08 h60
  text "X" at 13471.97,2441.08 h60
  text "2" at 13581.96,2441.08 h60
  text "1" at 13266.96,2439.58 h60
  text "3" at 13935.96,2439.58 h60
  text "X" at 12507.97,2293.39 h60
  text "RoHS" at 12635.96,2293.39 h60
  text "OTHER" at 13280.36,2293.39 h60
  text "PER ORDER" at 13677.42,2293.39 h60
  text "ALL BOARDS MUST MEET OR EXCEED UL94-V0 REQUIREMENTS." at 11361,2139.57 h60
  text "PCB MUST BEAR THE UL94V-0 UL REGISTERED MATERIAL ID NUMBER" at 11361,2023.5 h60
  text "ADDITIONAL REQUIREMENTS:" at 11333.46,1854.08 h60
  text "MICROSECTION:" at 11408.23,1746.95 h60
  text "YES" at 12313.96,1746.95 h60
  text "REQUIRED" at 13175.46,1602.62 h60
  text "BARE BOARD ELEC. TEST:" at 11408.23,1599.76 h60
  text "NONE" at 12713.96,1599.76 h60
  text "X" at 13057.46,1599.76 h60
  text "PER ORDER" at 13767.46,1599.76 h60
  text "X" at 11465.97,1454.39 h60
  text "7.87 MIL VIAS REQUIRE NON-CONDUCTIVE FILL AND PLANARIZE" at 11576.38,1394.82 h56
  text "XX MIL VIAS REQUIRE CONDUCTIVE FILL AND PLANARIZE" at 11584.38,1290.84 h60
  text "OUTER XX MIL TRACES REQUIRE 50 OHM SINGLE-ENDED IMPEDANCE" at 11583.39,1127.46 h58
  text "LAYER 2 & 3 (INNER LAYERS) XX MIL WIDE, XX MIL SPACE / TRACES REQUIRE 100 OHM DIFFERENTIAL IMPEDANCE" at 11575.39,891.74 h60
  text ".Layer_Name" at 577,-858.49 h60
M11 Gerber Information:
  lines w10: -292,-930.17 6308,-930.17 ; -292,-726.83 6310,-726.83 ; -292,-523.5 -292,-1133.5 3713,-1133.5 6310,-1133.5 6310,-523.5 -291.5,-523.5 -291.5,-1133.5 1284,-1133.5 ; 2173,-1133.5 2173,-523.5 ; 3440,-726.83 3440,-523.5 ; 4280,-726.83 4280,-523.5 ; 4902,-1140 4902,-937.17
  text "ALL ARTWORK VIEWED FROM TOP SIDE" at -228.5,-655.67 h60
  text "BOARD #:" at 2248,-655.67 h60
  text ".PRJ_Number" at 2793.5,-655.67 h60
  text "REV:" at 3638,-655.67 h60
  text ".PCB_Rev" at 3929.5,-655.67 h60
  text "SVN REV:" at 4476,-655.67 h60
  text ".VersionControl_RevNumber" at 4982,-655.67 h60
  text "LAYER NAME =" at -228.5,-858.49 h60
  text "TID #:" at 2248,-859 h60
  text ".TID" at 2793.5,-859 h60
  text "PLOT NAME =" at -228.5,-1064.34 h60
  text ".plot_File_Name" at 577,-1064.34 h60
  text "GENERATED    :" at 2250,-1064.34 h60
  text ".Print_Date" at 3119.5,-1064.34 h60
  text ".Print_Time" at 3848.5,-1064.34 h60
  text "TEXAS INSTRUMENTS" at 5113,-1064.34 h60
M12 Stackup:
  drawing of 295 lines, arcs and shapes, not listed
  text "Layer" at 6671.19,7643.01 h60
  text "Name" at 7081.11,7643.01 h60
  text "Material" at 8020.85,7643.01 h60
  text "Thickness" at 8880.62,7643.01 h60
  text "Constant" at 9530.45,7643.01 h60
  text "Board Layer Stack" at 10100.31,7643.01 h60
  text "Top Overlay" at 7081.11,7523.01 h60
  text "Top Solder" at 7081.11,7403.01 h60
  text "Solder Resist" at 8020.85,7403.01 h60
  text "0.40mil" at 8880.62,7403.01 h60
  text "3.5" at 9530.45,7403.01 h60
  text "1" at 6671.19,7283.01 h60
  text "Top Layer" at 7081.11,7283.01 h60
  text "2.80mil" at 8880.62,7283.01 h60
  text "Dielectric 1" at 7081.11,7163.01 h60
  text "FR-4 High Tg" at 8020.85,7163.01 h60
  text "8.00mil" at 8880.62,7163.01 h60
  text "4.2" at 9530.45,7163.01 h60
  text "2" at 6671.19,7043.01 h60
  text "Signal Layer 1" at 7081.11,7043.01 h60
  text "2.76mil" at 8880.62,7043.01 h60
  text "Dielectric 2" at 7081.11,6923.01 h60
  text "FR-4 High Tg" at 8020.85,6923.01 h60
  text "37.20mil" at 8880.62,6923.01 h60
  text "4.2" at 9530.45,6923.01 h60
  text "3" at 6671.19,6803.01 h60
  text "Signal Layer 2" at 7081.11,6803.01 h60
  text "2.76mil" at 8880.62,6803.01 h60
  text "Dielectric 3" at 7081.11,6683.01 h60
  text "FR-4 High Tg" at 8020.85,6683.01 h60
  text "8.00mil" at 8880.62,6683.01 h60
  text "4.2" at 9530.45,6683.01 h60
  text "4" at 6671.19,6563.01 h60
  text "Bottom Layer" at 7081.11,6563.01 h60
  text "2.80mil" at 8880.62,6563.01 h60
  text "Bottom Solder" at 7081.11,6443.01 h60
  text "Solder Resist" at 8020.85,6443.01 h60
  text "0.40mil" at 8880.62,6443.01 h60
  text "3.5" at 9530.45,6443.01 h60
  text "Bottom Overlay" at 7081.11,6323.01 h60
  text "Total board thickness:" at 6671.19,6203.01 h60
  text "65.11mil" at 8880.62,6203.01 h60
  text ".Layer_Name" at 577,-858.49 h60
M13 Component Bodies Top:
  text ".Layer_Name" at 577,-858.49 h60
M14 Component Bodies Bottom:
  text ".Layer_Name" at 577,-858.49 h60
M15 Courtyards Top:
  text ".Layer_Name" at 577,-858.49 h60
M16 Courtyards Bottom:
  text ".Layer_Name" at 577,-858.49 h60
Drill Drawing:
  circle w10: c5732.63,2876.26 r16.56
  circle w10: c5732.63,2876.26 r27.59
  circle w10: c5732.63,2255.38 r27.59
  lines w10: 5705.04,1979.43 5760.23,1979.43 5760.23,2034.62 5705.04,2034.62 5705.04,1979.43 ; 5705.04,2117.4 5718.83,2117.4 5718.83,2103.6 5746.43,2103.6 5746.43,2117.4 5760.23,2117.4 5760.23,2145 5746.43,2145 5746.43,2158.79 5718.83,2158.79 5718.83,2145 5705.04,2145 5705.04,2117.4 ; 5705.04,2365.75 5718.83,2365.75 5732.63,2351.96 5746.43,2365.75 5760.23,2365.75 5746.43,2379.55 5760.23,2393.35 5746.43,2393.35 5732.63,2407.15 5718.83,2393.35 5705.04,2393.35 5718.83,2379.55 5705.04,2365.75 ; 5705.04,2503.73 5732.63,2476.13 5760.23,2503.73 5732.63,2531.32 5705.04,2503.73 ; 5705.04,2600.31 5732.63,2614.11 5760.23,2600.31 5746.43,2627.9 5760.23,2655.5 5732.63,2641.7 5705.04,2655.5 5718.83,2627.9 5705.04,2600.31 ; 5705.04,2779.67 5760.23,2779.67 5732.63,2724.48 5705.04,2779.67 ; 5705.04,2972.84 5705.04,2986.63 5718.83,3000.43 5705.04,3014.23 5705.04,3028.03 5718.83,3028.03 5732.63,3014.23 5746.43,3028.03 5760.23,3028.03 5760.23,3014.23 5746.43,3000.43 5760.23,2986.63 5760.23,2972.84 5746.43,2972.84 5732.63,2986.63 5718.83,2972.84 5705.04,2972.84 ; 5705.04,3097.01 5760.23,3097.01 5760.23,3152.2 5705.04,3152.2 5705.04,3097.01 ; 5716.07,3108.05 5749.19,3108.05 5749.19,3141.16 5716.07,3141.16 5716.07,3108.05
  lines w12: 5655,1942.18 8837.27,1942.18 ; 5655,3183.94 8837.27,3183.94 ; 5992.72,1818 5992.72,3308.11 ; 6321.57,1818 6321.57,3308.11 ; 6913.58,1818 6913.58,3308.11 ; 7172.58,1818 7172.58,3308.11 ; 7547.63,1818 7547.63,3308.11 ; 8271.01,1818 8271.01,3308.11 ; 5655,1818 8837.27,1818 8837.27,3308.11 5655,3308.11 5655,1818
  text "Symbol" at 5729.51,3221.19 h72
  text "Count" at 6029.97,3221.19 h72
  text "Hole Size" at 6358.82,3221.19 h72
  text "Plated" at 6950.83,3221.19 h72
  text "Hole Type" at 7209.83,3221.19 h72
  text "Drill Layer Pair" at 7584.88,3221.19 h72
  text "Hole Tolerance" at 8308.26,3221.19 h72
  text "534" at 6029.97,3097.01 h60
  text "7.87mil (0.200mm)" at 6358.82,3097.01 h60
  text "PTH" at 6950.83,3097.01 h60
  text "Round" at 7209.83,3097.01 h60
  text "Top Layer - Bottom Layer" at 7584.88,3097.01 h60
  text "830" at 6029.97,2972.84 h60
  text "8.00mil (0.203mm)" at 6358.82,2972.84 h60
  text "PTH" at 6950.83,2972.84 h60
  text "Round" at 7209.83,2972.84 h60
  text "Top Layer - Bottom Layer" at 7584.88,2972.84 h60
  text "1" at 6029.97,2848.66 h60
  text "16.00mil (0.406mm)" at 6358.82,2848.66 h60
  text "PTH" at 6950.83,2848.66 h60
  text "Round" at 7209.83,2848.66 h60
  text "Top Layer - Bottom Layer" at 7584.88,2848.66 h60
  text "17" at 6029.97,2724.48 h60
  text "40.00mil (1.016mm)" at 6358.82,2724.48 h60
  text "PTH" at 6950.83,2724.48 h60
  text "Round" at 7209.83,2724.48 h60
  text "Top Layer - Bottom Layer" at 7584.88,2724.48 h60
  text "6" at 6029.97,2600.31 h60
  text "40.16mil (1.020mm)" at 6358.82,2600.31 h60
  text "PTH" at 6950.83,2600.31 h60
  text "Round" at 7209.83,2600.31 h60
  text "Top Layer - Bottom Layer" at 7584.88,2600.31 h60
  text "5" at 6029.97,2476.13 h60
  text "43.31mil (1.100mm)" at 6358.82,2476.13 h60
  text "PTH" at 6950.83,2476.13 h60
  text "Round" at 7209.83,2476.13 h60
  text "Top Layer - Bottom Layer" at 7584.88,2476.13 h60
  text "+/-1.97mil" at 8308.26,2476.13 h60
  text "56" at 6029.97,2351.96 h60
  text "45.28mil (1.150mm)" at 6358.82,2351.96 h60
  text "PTH" at 6950.83,2351.96 h60
  text "Round" at 7209.83,2351.96 h60
  text "Top Layer - Bottom Layer" at 7584.88,2351.96 h60
  text "6" at 6029.97,2227.78 h60
  text "63.00mil (1.600mm)" at 6358.82,2227.78 h60
  text "PTH" at 6950.83,2227.78 h60
  text "Round" at 7209.83,2227.78 h60
  text "Top Layer - Bottom Layer" at 7584.88,2227.78 h60
  text "4" at 6029.97,2103.6 h60
  text "125.98mil (3.200mm)" at 6358.82,2103.6 h60
  text "PTH" at 6950.83,2103.6 h60
  text "Round" at 7209.83,2103.6 h60
  text "Top Layer - Bottom Layer" at 7584.88,2103.6 h60
  text "4" at 6029.97,1979.43 h60
  text "270.00mil (6.858mm)" at 6358.82,1979.43 h60
  text "PTH" at 6950.83,1979.43 h60
  text "Round" at 7209.83,1979.43 h60
  text "Top Layer - Bottom Layer" at 7584.88,1979.43 h60
  text "1463 Total" at 6029.97,1855.25 h60
  text ".Layer_Name" at 577,-858.49 h60
M17 Embedded Cavity:
  text ".Layer_Name" at 577,-858.49 h60
M18 Embedded Assembly:
  text ".Layer_Name" at 577,-858.49 h60
M19 Embedded Keepout:
  text ".Layer_Name" at 577,-858.49 h60

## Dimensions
0,3200 to 0,0 on M2 Board Dimensions
0,0 to 5500,0 on M2 Board Dimensions
0,-400 to 1000,-400 on M2 Board Dimensions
